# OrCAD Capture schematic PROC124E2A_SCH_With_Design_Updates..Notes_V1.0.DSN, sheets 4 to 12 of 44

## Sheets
4 12. SOC POWER SUPPLY PMIC: size C; title: SOC POWER SUPPLY PMIC
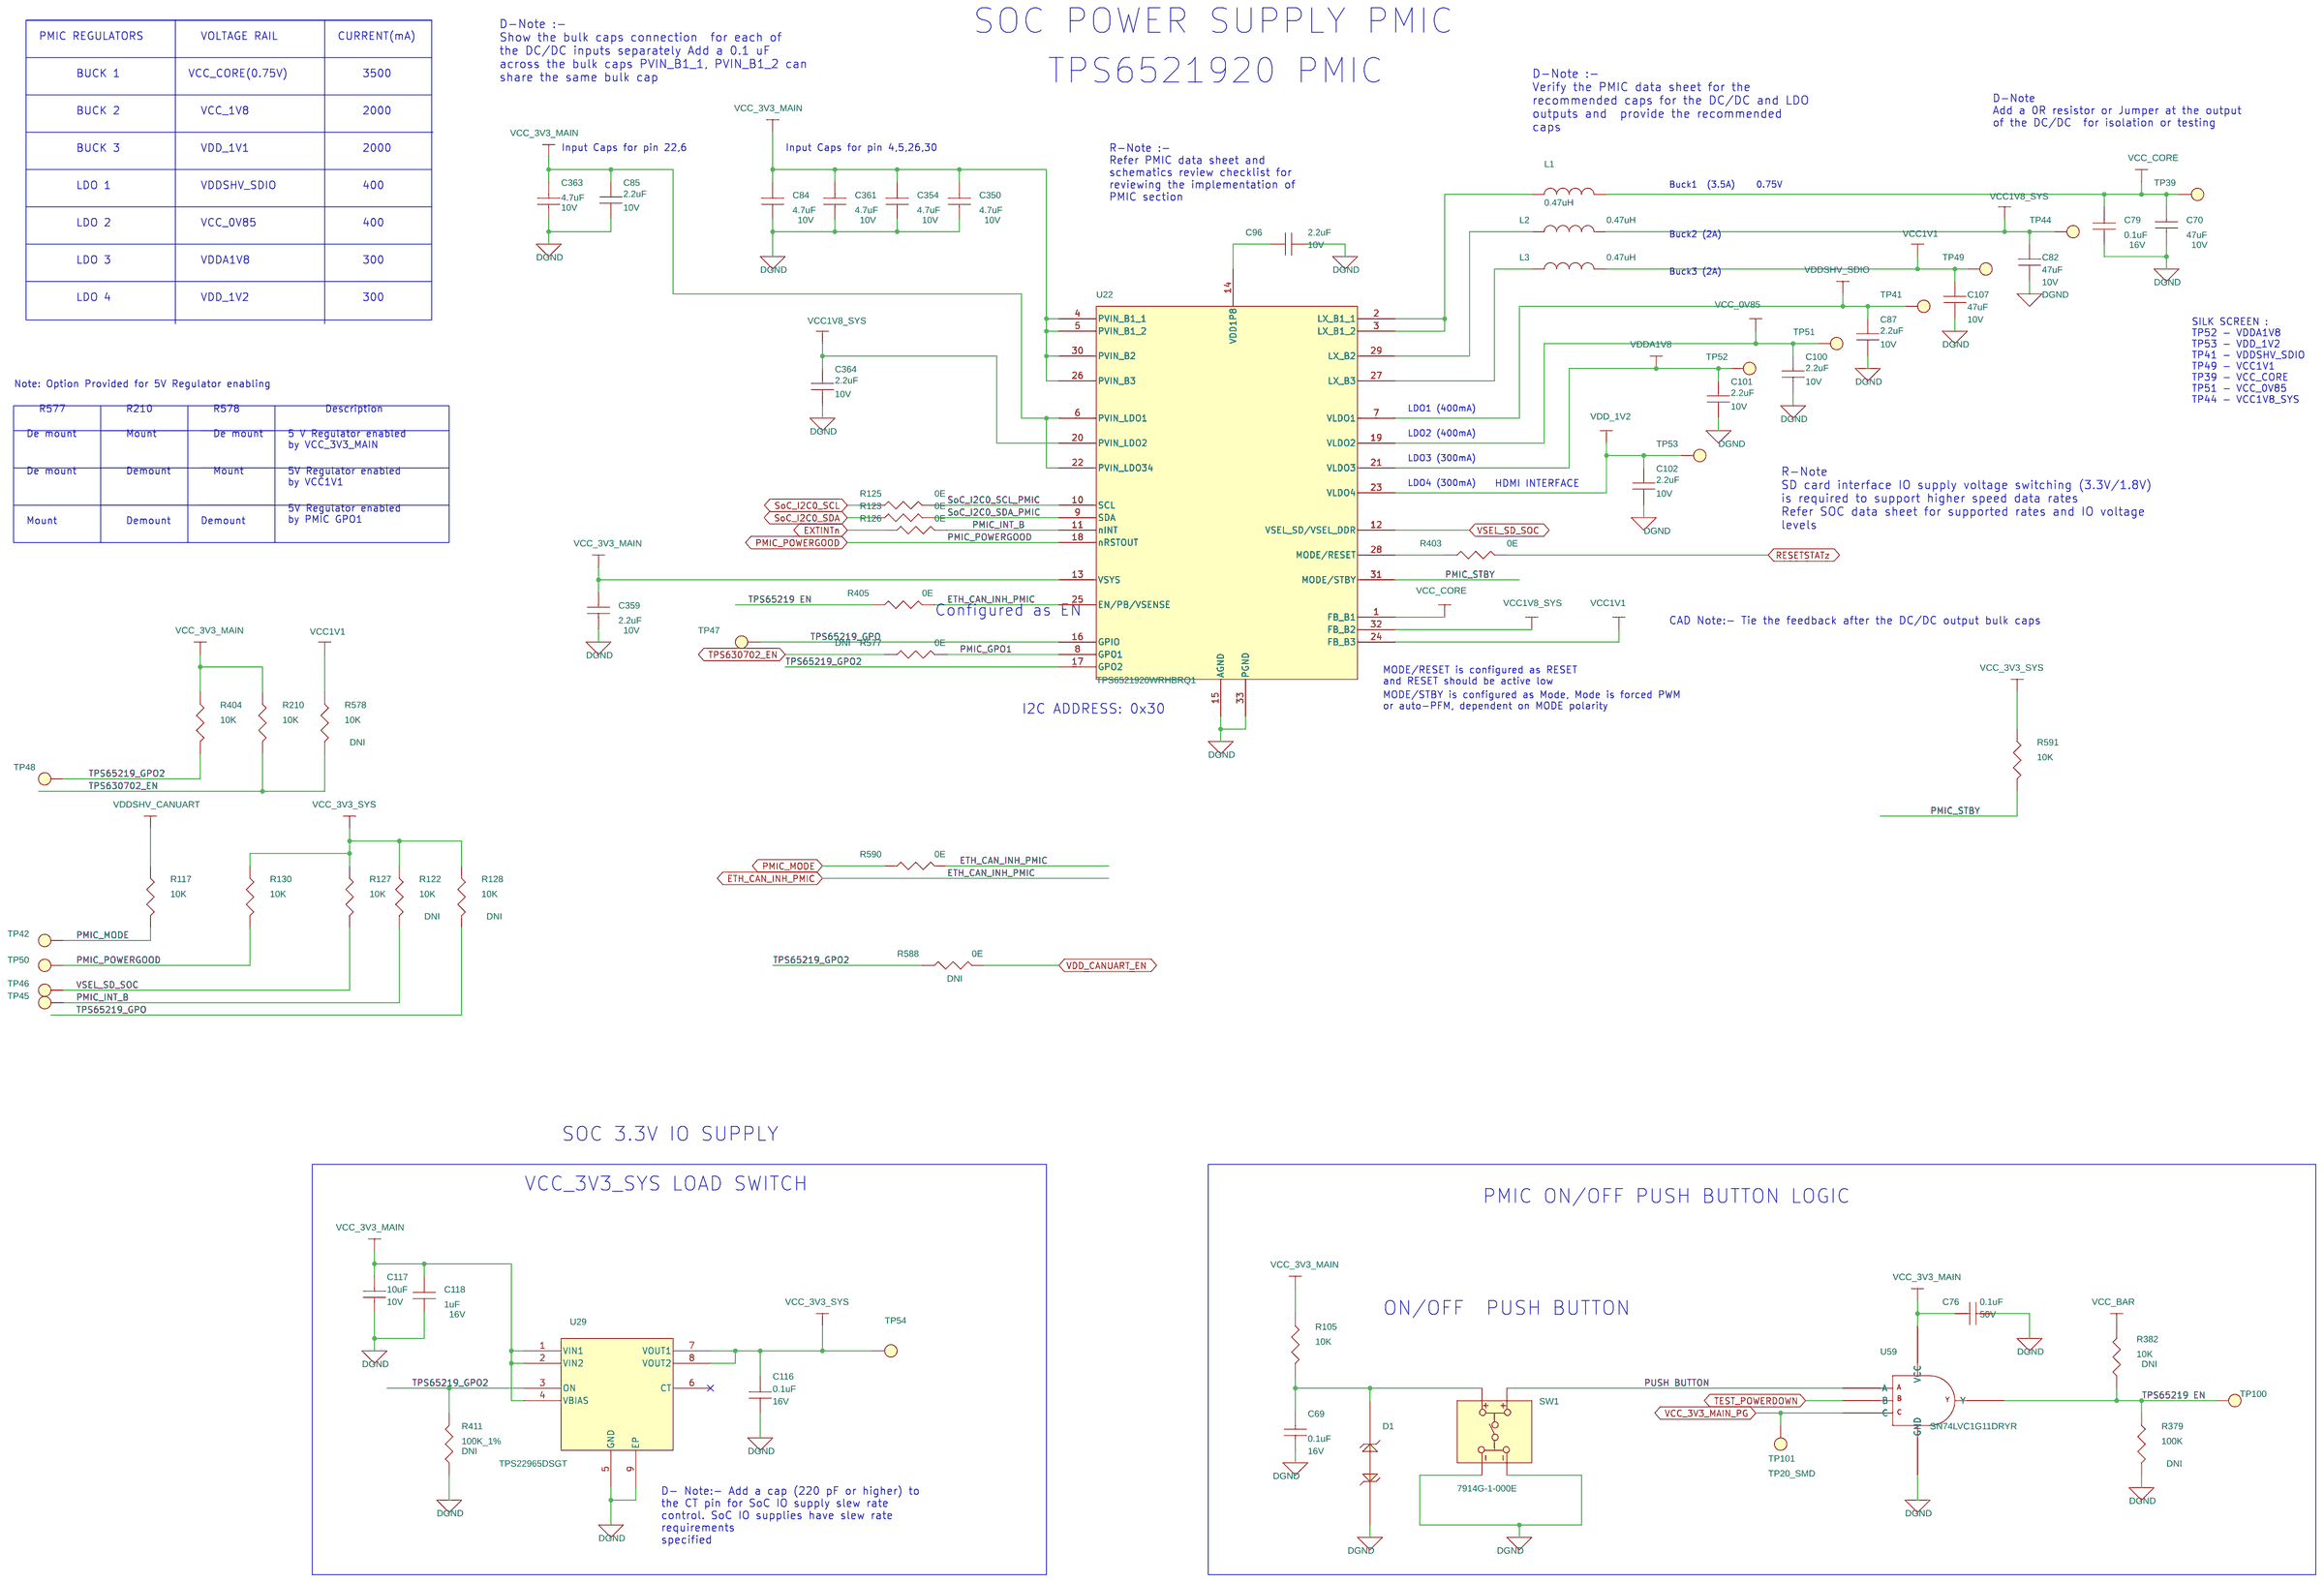
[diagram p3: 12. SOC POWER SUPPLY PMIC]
5 01. TABLE OF CONTENTS: title: TABLE OF CONTENTS
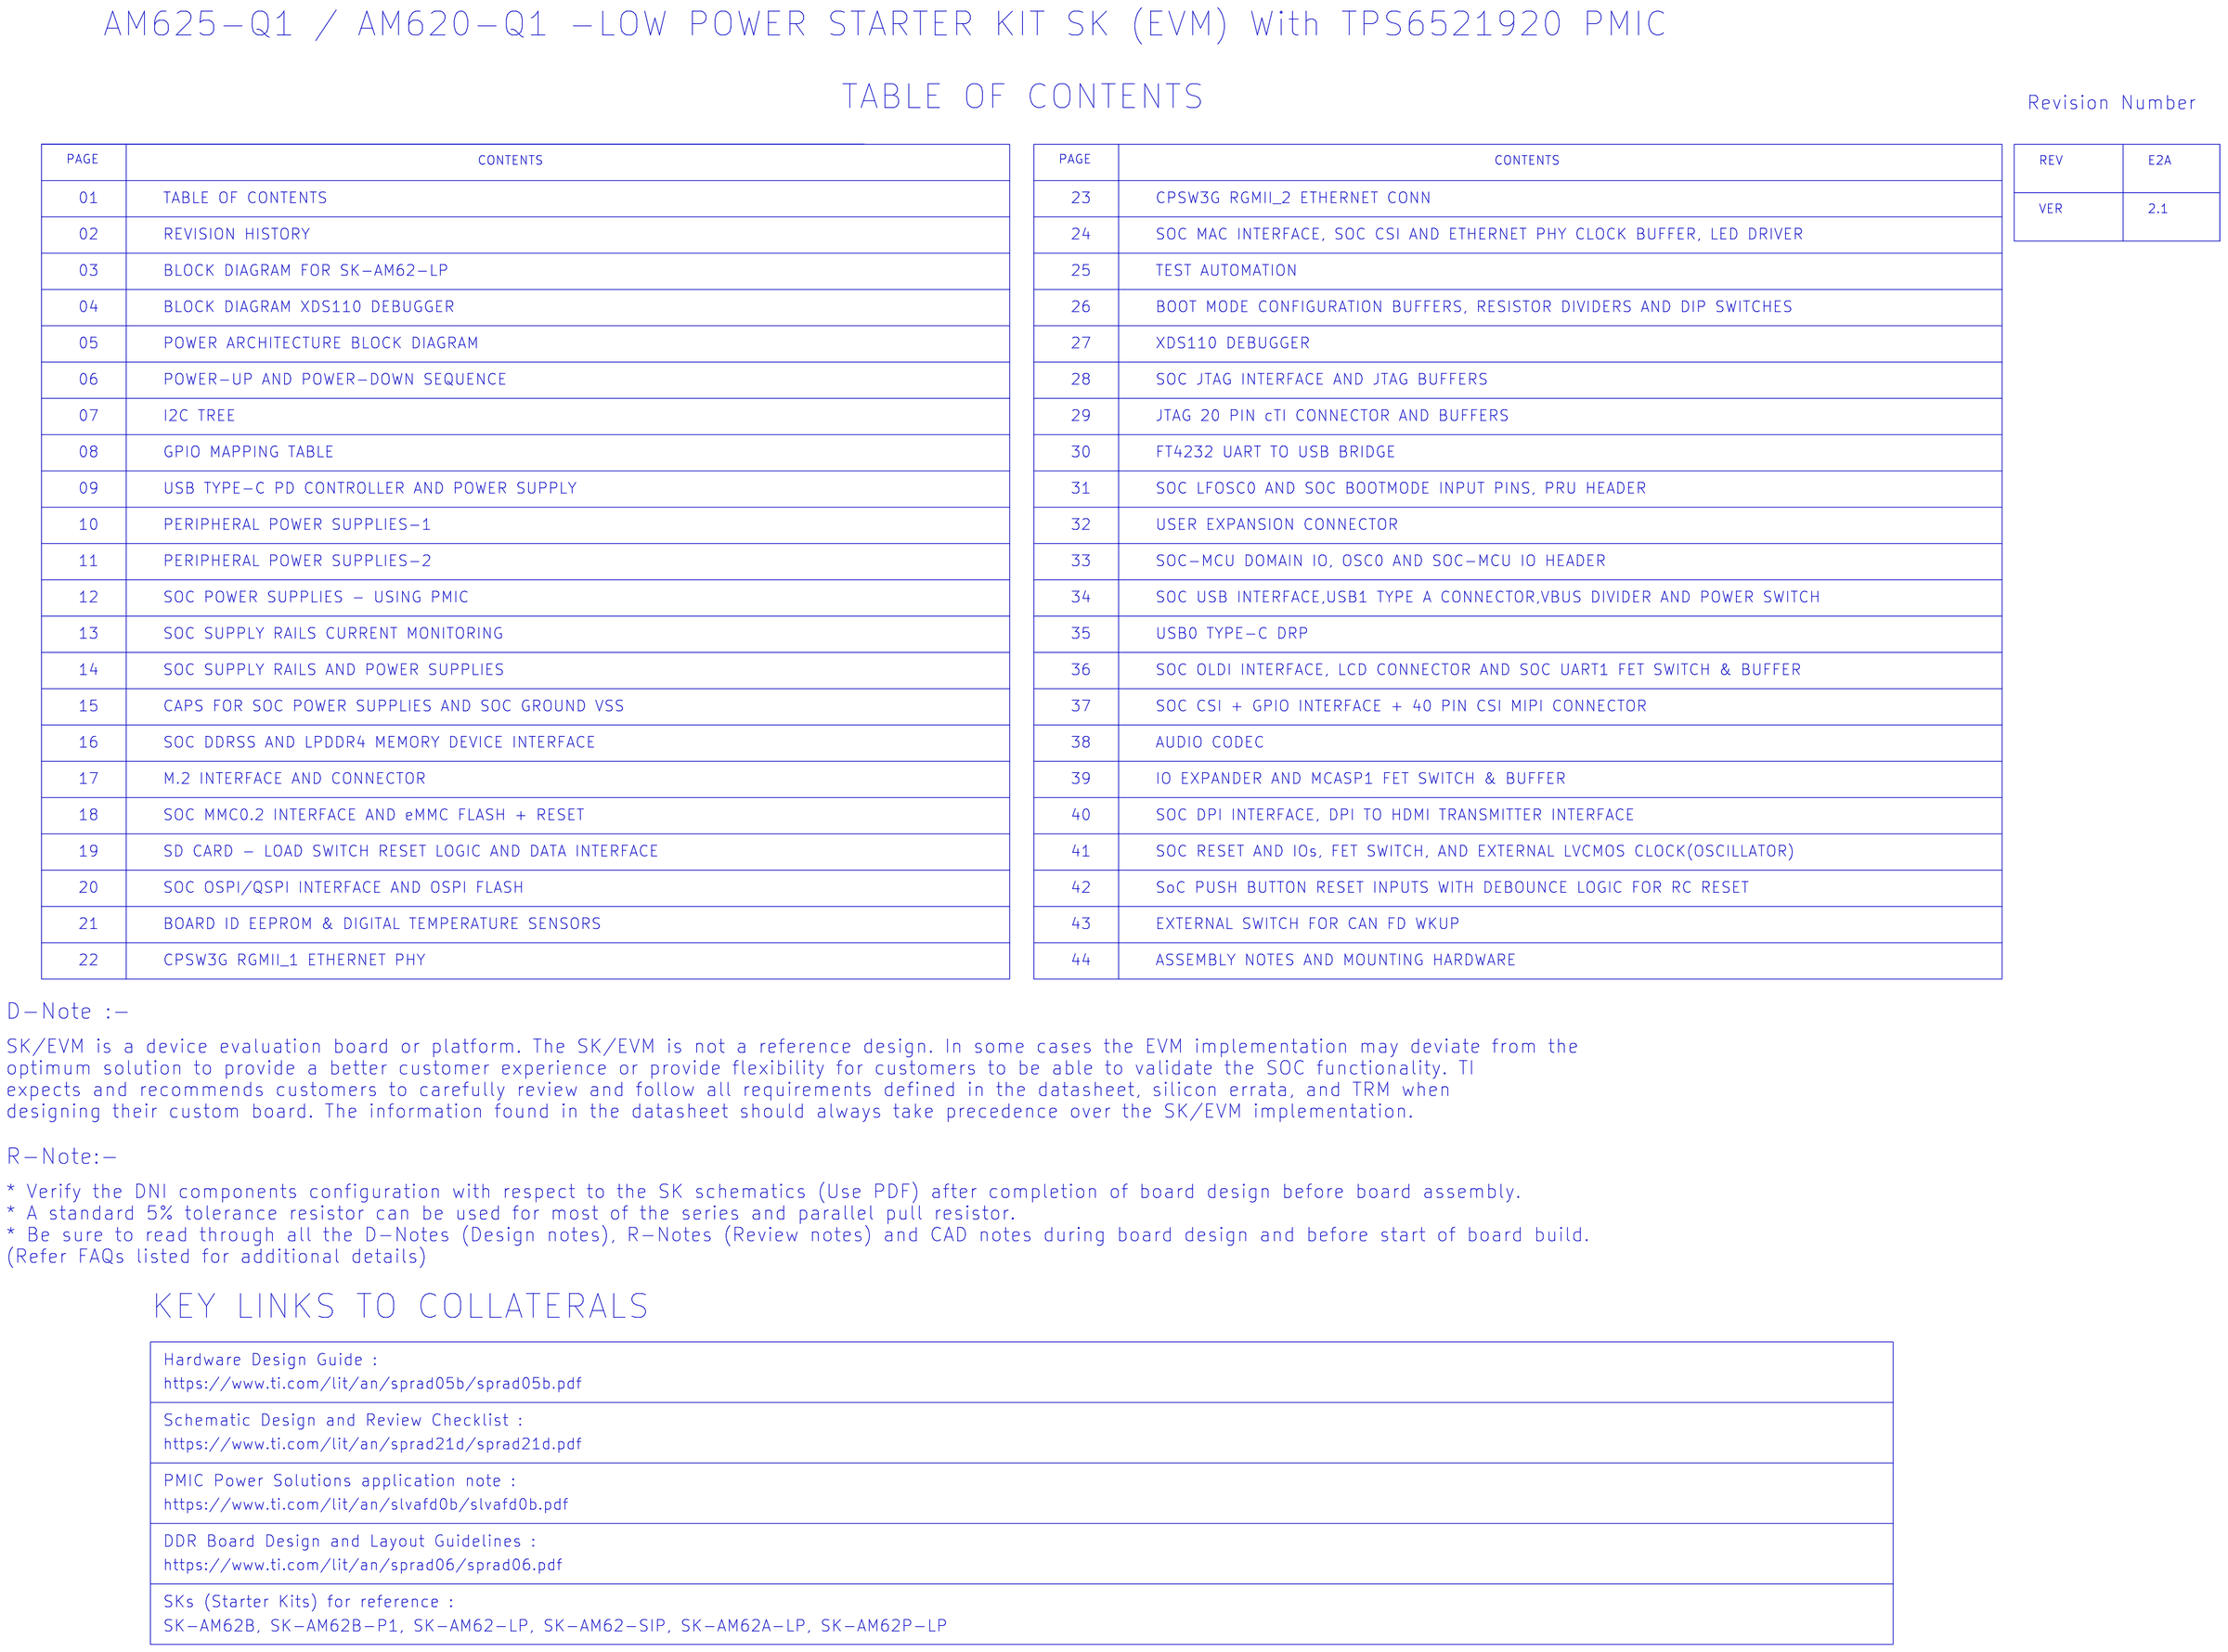
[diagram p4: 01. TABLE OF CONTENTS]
6 02. REVISION HISTORY: title: REVISION HISTORY
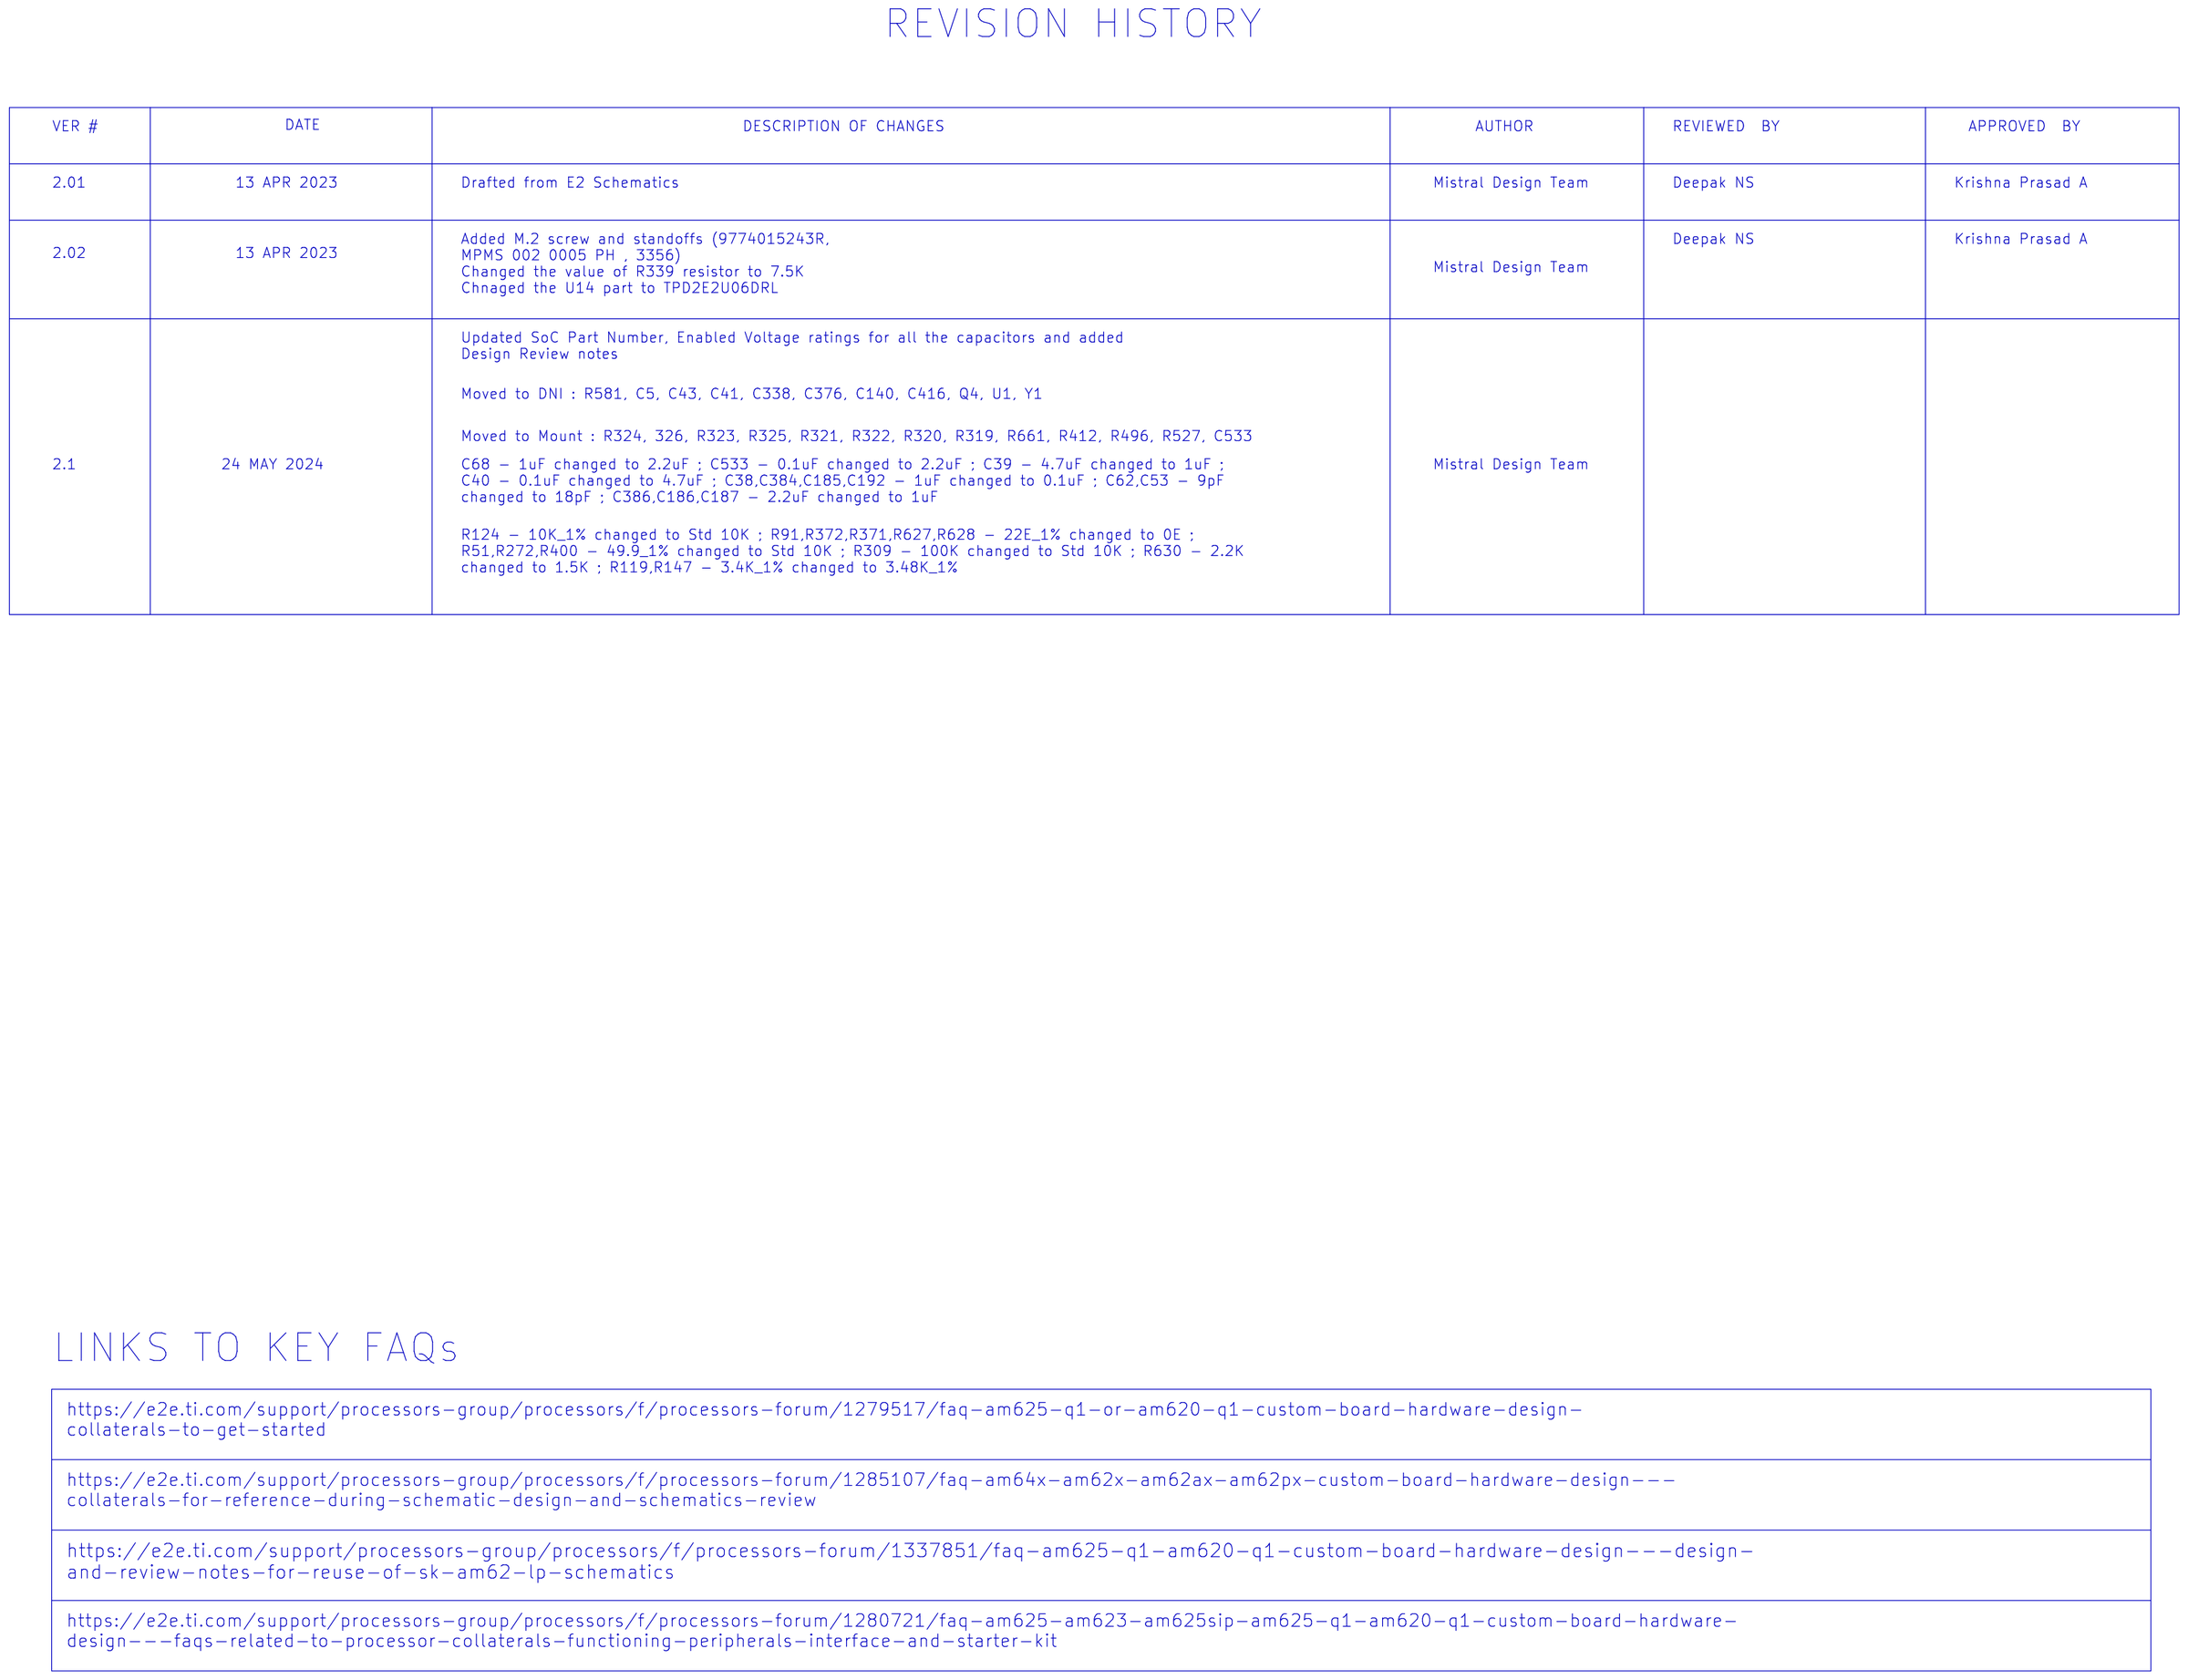
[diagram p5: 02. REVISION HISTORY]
7 03. BLOCK DGM AM62X-LP-SKEVM: title: BLOCK DIAGRAM AM62Q-LP_ SKEVM
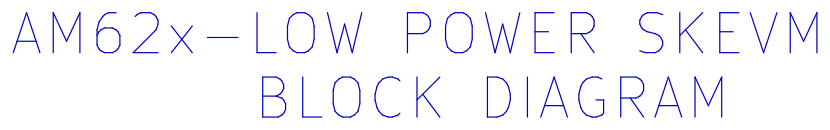
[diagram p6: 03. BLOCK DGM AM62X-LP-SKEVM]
8 04. BLOCK DIAGRAM_XDS110: title: BLOCK DIAGRAM_XDS110
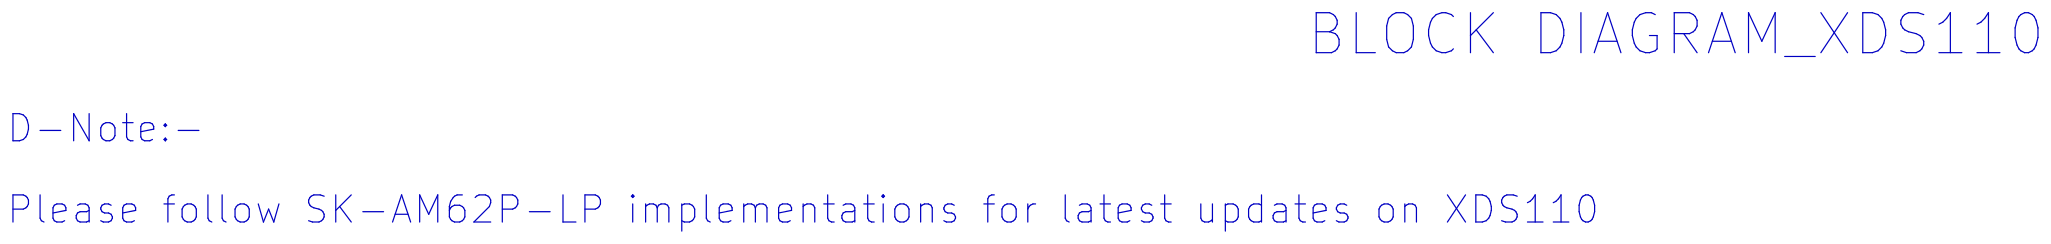
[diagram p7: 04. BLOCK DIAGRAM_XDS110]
9 05. POWER BLOCK DGM: title: POWER BLOCK DGM
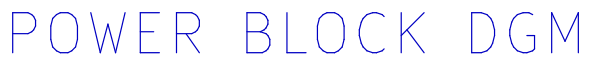
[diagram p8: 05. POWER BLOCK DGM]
10 06. POWER SEQUENCE: title: POWER SEQUENCE
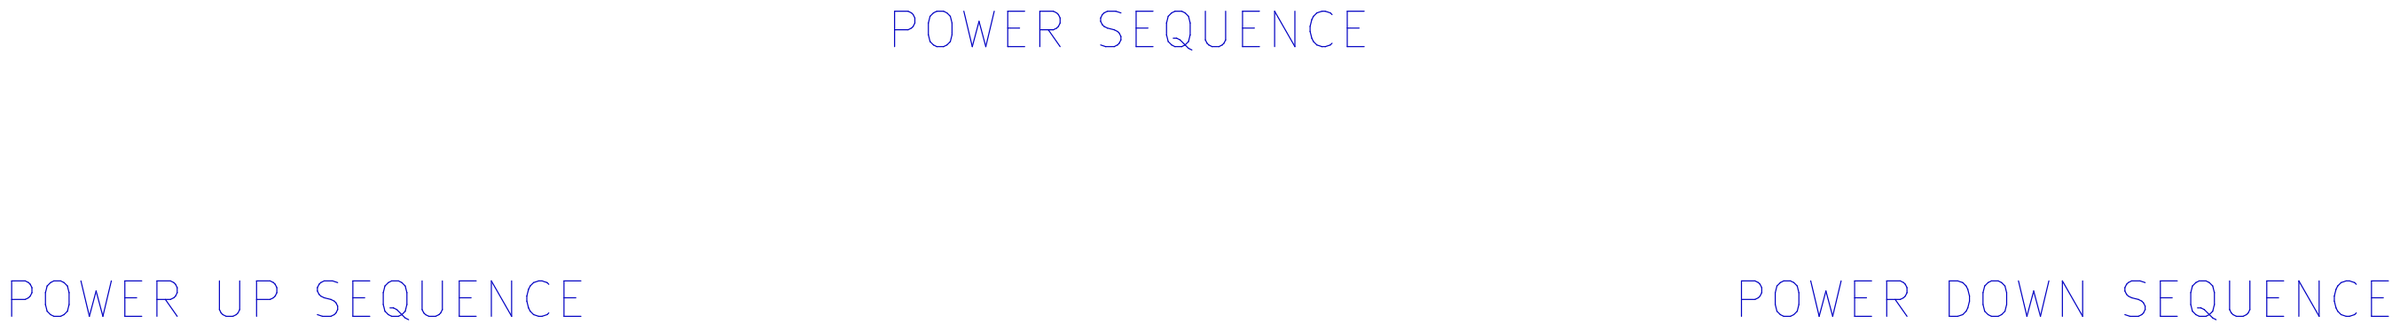
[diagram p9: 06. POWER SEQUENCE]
11 07. I2C TREE: title: I2C TREE
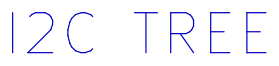
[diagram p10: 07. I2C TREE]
12 08. GPIO MAPPING TABLE: title: GPIO MAPPING TABLE
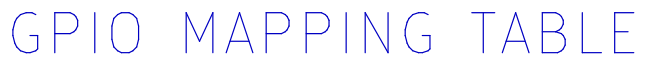
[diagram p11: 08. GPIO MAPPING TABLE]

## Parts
C69  0.1uF  [CAP0201_0-5]
C70  47uF  [CAP1206_2]
C76  0.1uF  [CAP0402_0-75]
C79  0.1uF  [CAP0201_0-5]
C82  47uF  [CAP1206_2]
C84  4.7uF  [CAP0402_0-75]
C85  2.2uF  [CAP0201_0-5]
C87  2.2uF  [CAP0201_0-5]
C96  2.2uF  [CAP0201_0-5]
C100  2.2uF  [CAP0201_0-5]
C101  2.2uF  [CAP0201_0-5]
C102  2.2uF  [CAP0201_0-5]
C107  47uF  [CAP1206_2]
C116  0.1uF  [CAP0201_0-5]
C117  10uF  [CAP0402_0-75]
C118  1uF  [CAP0201_0-5]
C350  4.7uF  [CAP0402_0-75]
C354  4.7uF  [CAP0402_0-75]
C359  2.2uF  [CAP0201_0-5]
C361  4.7uF  [CAP0402_0-75]
C363  4.7uF  [CAP0402_0-75]
C364  2.2uF  [CAP0201_0-5]
D1  TPD1E10B06DPYR  [DIO_DFN0402_0-5]
L1  0.47uH  [IND1008_1-2]
L2  0.47uH  [IND0806_1-2]
L3  0.47uH  [IND0806_1-2]
R105  10K  [RES0201_0-5]
R117  10K  [RES0201_0-5]
R122  10K  [RES0201_0-5]
R123  0E  [RES0201_0-5]
R125  0E  [RES0201_0-5]
R126  0E  [RES0201_0-5]
R127  10K  [RES0201_0-5]
R128  10K  [RES0201_0-5]
R130  10K  [RES0201_0-5]
R210  10K  [RES0201_0-5]
R379  100K  [RES0201_0-5]
R382  10K  [RES0201_0-5]
R403  0E  [RES0201_0-5]
R404  10K  [RES0201_0-5]
R405  0E  [RES0201_0-5]
R411  100K_1%  [RES0402_0-5]
R577  0E  [RES0201_0-5]
R578  10K  [RES0201_0-5]
R588  0E  [RES0201_0-5]
R590  0E  [RES0201_0-5]
R591  10K  [RES0201_0-5]
SW1  7914G-1-000E  [SW4_100X216_200X200_SMD_4-2]
TP39  TP20_SMD  [TP20_SMD]
TP41  TP20_SMD  [TP20_SMD]
TP42  TP20_SMD  [TP20_SMD]
TP44  TP20_SMD  [TP20_SMD]
TP45  TP20_SMD  [TP20_SMD]
TP46  TP20_SMD  [TP20_SMD]
TP47  TP20_SMD  [TP20_SMD]
TP48  TP20_SMD  [TP20_SMD]
TP49  TP20_SMD  [TP20_SMD]
TP50  TP20_SMD  [TP20_SMD]
TP51  TP20_SMD  [TP20_SMD]
TP52  TP20_SMD  [TP20_SMD]
TP53  TP20_SMD  [TP20_SMD]
TP54  TP20_SMD  [TP20_SMD]
TP100  TP20_SMD  [TP20_SMD]
TP101  TP20_SMD  [TP20_SMD]
U22  TPS6521920WRHBRQ1  [QFN32_19-68_200X200_1_EP3-8]
U29  TPS22965DSGT  [WSON8_19-68_80X80_0-8]
U59  SN74LVC1G11DRYR  [SON6_SN74LVC2G17_40X60_0-6]

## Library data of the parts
C69 C116 = CAP: CAP CERAMIC 0.1uF 16V 10% X5R 0201; Alt_Mfr_name: YAGEO AMERICA; Alt_Mfr_part_number: CC0402KRX5R8BB104; Chkd/date: MANIRAJA/230118; Crtd /date: MANIRAJA/230118; Custom_Duty: 15%; Customs_HS_Code: 85322990; Distributor_name: DIGIKEY; Distributor_part_number: 490-14305-1-ND; Footprint Path: Y:\MIS_DATABASE\Library\ALTIUM_TOOL\PCB_FOOTPRINTS\Altium_Footprint_Lib.PcbLib; Height: 0.33MM; Library Path: Y:\MIS_DATABASE\Library\ALTIUM_TOOL\SCHEMATICS_PARTS\MS_DISCRETE_Library.schlib; Mfr_name: MURATA; Mfr_part_number: GRM033R61C104KE14D; Mistral Part No: 120009030072-R; Package: 0201; Part_type: CAPACITORS\CERAMIC; Project: TI_MAXIE_CPB; RoHS: RoHS; Temperature: -55°C+85°C; Tolerance: 10%; Voltage: 16V; Wattage: NA; Weight: 0.33mg; Datasheet: Y:\MIS_DATABASE\DATASHEETS\CAPACITORS\GRM033R61C104KE14.PDF
C70 = CAP: CAP CERAMIC 47uF 10V 10% X5R 1206; Chkd/date: MANIRAJA/260219; Crtd /date: JEBRAN/090316; Custom_Duty: 15%; Customs_HS_Code: 85322990; Distributor_name: DIGIKEY; Distributor_part_number: 490-9673-1-ND; Footprint Path: Y:\MIS_DATABASE\Library\ALTIUM_TOOL\PCB_FOOTPRINTS\Altium_Footprint_Lib.PcbLib; Height: 1.80MM; Library Path: Y:\MIS_DATABASE\Library\ALTIUM_TOOL\SCHEMATICS_PARTS\MS_DISCRETE_Library.schlib; Manufacturer: MURATA; Mfr_name: MURATA; Mfr_part_number: GRM31CR61A476KE15L; Mistral Part No: 120019020018-R; Package: 1206; Part_type: CAPACITORS\CERAMIC; Project: RCI_DLS_CARD; RoHS: RoHS; Temperature: -55°C+85°C; Tolerance: 10%; Voltage: 10V; Wattage: NA; Weight: 40mg; Datasheet: Y:\MIS_DATABASE\DATASHEETS\CAPACITORS\MURATA-GXX-SER_NOV17.PDF
C76 = CAP: CAP CERAMIC 0.1uF 50V 10% X7R 0402; Alt_Mfr_name: YAGEO AMERICA; Alt_Mfr_part_number: CC0402KRX5R8BB104; Chkd/date: MANIRAJA/261020; Crtd /date: ALVY/211020; Custom_Duty: 15%; Customs_HS_Code: 85322990; Distributor_name: DIGIKEY; Distributor_part_number: 490-10700-1-ND; Footprint Path: Y:\MIS_DATABASE\Library\ALTIUM_TOOL\PCB_FOOTPRINTS\Altium_Footprint_Lib.PcbLib; Height: 0.55MM; Library Path: Y:\MIS_DATABASE\Library\ALTIUM_TOOL\SCHEMATICS_PARTS\MS_DISCRETE_Library.schlib; Mfr_name: MURATA; Mfr_part_number: GRM155R71H104KE14D; Mistral Part No: 120011100014-R; Package: 0402; Part_type: CAPACITORS\CERAMIC; Project: J7_CP; RoHS: RoHS; Temperature: -55°C+125°C; Tolerance: 10%; Voltage: 50V; Wattage: NA; Weight: 3.1mg; Datasheet: Y:\MIS_DATABASE\DATASHEETS\CAPACITORS\GRM155R71H104KE14.PDF
C79 = CAP: CAP CERAMIC 0.1uF 16V 10% X5R 0201; Chkd/date: MANIRAJA/230118; Crtd /date: MANIRAJA/230118; Custom_Duty: 15%; Customs_HS_Code: 85322990; Distributor_name: DIGIKEY; Distributor_part_number: 490-14305-1-ND; Footprint Path: Y:\MIS_DATABASE\Library\ALTIUM_TOOL\PCB_FOOTPRINTS\Altium_Footprint_Lib.PcbLib; Height: 0.33MM; Library Path: Y:\MIS_DATABASE\Library\ALTIUM_TOOL\SCHEMATICS_PARTS\MS_DISCRETE_Library.schlib; Mfr_name: MURATA; Mfr_part_number: GRM033R61C104KE14D; Mistral Part No: 120009030072-R; Package: 0201; Part_type: CAPACITORS\CERAMIC; Project: TI_MAXIE_CPB; RoHS: RoHS; Temperature: -55°C+85°C; Tolerance: 10%; Voltage: 16V; Wattage: NA; Weight: 0.33mg; Datasheet: Y:\MIS_DATABASE\DATASHEETS\CAPACITORS\GRM033R61C104KE14.PDF
C82 C107 = CAP: CAP CERAMIC 47uF 10V 10% X5R 1206; Chkd/date: MANIRAJA/260219; Crtd /date: JEBRAN/090316; Custom_Duty: 15%; Customs_HS_Code: 85322990; Distributor_name: DIGIKEY; Distributor_part_number: 490-9673-1-ND; Footprint Path: Y:\MIS_DATABASE\Library\ALTIUM_TOOL\PCB_FOOTPRINTS\Altium_Footprint_Lib.PcbLib; Height: 1.80MM; Library Path: Y:\MIS_DATABASE\Library\ALTIUM_TOOL\SCHEMATICS_PARTS\MS_DISCRETE_Library.schlib; Mfr_name: MURATA; Mfr_part_number: GRM31CR61A476KE15L; Mistral Part No: 120019020018-R; Package: 1206; Part_type: CAPACITORS\CERAMIC; Project: RCI_DLS_CARD; RoHS: RoHS; Temperature: -55°C+85°C; Tolerance: 10%; Voltage: 10V; Wattage: NA; Weight: 40mg; Datasheet: Y:\MIS_DATABASE\DATASHEETS\CAPACITORS\MURATA-GXX-SER_NOV17.PDF
C84 C350 C354 C361 C363 = CAP: CAP CERAMIC 4.7uF 10V 20% X5R 0402; Chkd/date: MANIRAJA/110718; Crtd /date: ALVY/110718; Custom_Duty: 15%; Customs_HS_Code: 85322990; Distributor_name: DIGIKEY; Distributor_part_number: 490-14306-1-ND; Footprint Path: Y:\MIS_DATABASE\Library\ALTIUM_TOOL\PCB_FOOTPRINTS\Altium_Footprint_Lib.PcbLib; Height: 0.65MM; Library Path: Y:\MIS_DATABASE\Library\ALTIUM_TOOL\SCHEMATICS_PARTS\MS_DISCRETE_Library.schlib; Mfr_name: MURATA; Mfr_part_number: GRM155R61A475MEAAD; Mistral Part No: 120012060002-R; Package: 0402; Part_type: CAPACITORS\CERAMIC; Project: TI_J7SVB_PCIE_ADD-ON-CARD; RoHS: RoHS; Temperature: -55°C+85°C; Tolerance: 20%; Voltage: 10V; Wattage: NA; Weight: 14mg; Datasheet: Y:\MIS_DATABASE\DATASHEETS\CAPACITORS\GRM155R61A475MEAAD.PDF
C85 C87 C96 C100-C102 C364 = CAP: CAP CERAMIC 2.2uF 10V 10% X5R 0201; Chkd/date: MANIRAJA/220918; Crtd /date: MANIRAJA/220918; Custom_Duty: 15%; Customs_HS_Code: 85322990; Distributor_name: DIGIKEY; Distributor_part_number: 490-13227-1-ND; Footprint Path: Y:\MIS_DATABASE\Library\ALTIUM_TOOL\PCB_FOOTPRINTS\Altium_Footprint_Lib.PcbLib; Height: 0.39MM; Library Path: Y:\MIS_DATABASE\Library\ALTIUM_TOOL\SCHEMATICS_PARTS\MS_DISCRETE_Library.schlib; Mfr_name: MURATA; Mfr_part_number: GRM033R61A225KE47D; Mistral Part No: 120018090044-R; Package: 0201; Part_type: CAPACITORS\CERAMIC; Project: TI_60GHz-AOP; RoHS: RoHS; Temperature: -55°C+85°C; Tolerance: 10%; Voltage: 10V; Wattage: NA; Weight: 0.33mg; Datasheet: Y:\MIS_DATABASE\DATASHEETS\CAPACITORS\GRM033R61A225KE47D.PDF
C117 = CAP: CAP CERAMIC 10uF 10V 20% X5R 0402; Chkd/date: MANIRAJA/300520; Crtd /date: ALVY/260520; Custom_Duty: 15%; Customs_HS_Code: 85322990; Distributor_name: DIGIKEY; Distributor_part_number: 490-GRM155R61A106ME11DTR-ND; Footprint Path: Y:\MIS_DATABASE\Library\ALTIUM_TOOL\PCB_FOOTPRINTS\Altium_Footprint_Lib.PcbLib; Height: 0.55MM; Library Path: Y:\MIS_DATABASE\Library\ALTIUM_TOOL\SCHEMATICS_PARTS\MS_DISCRETE_Library.schlib; Mfr_name: MURATA; Mfr_part_number: GRM155R61A106ME11D; Mistral Part No: 120013110019-R; Package: 0402; Part_type: CAPACITORS\CERAMIC; Project: QCS610_NANOSOM; RoHS: RoHS; Temperature: -55°C+85°C; Tolerance: 20%; Voltage: 10V; Wattage: NA; Weight: 3.1mg; Datasheet: Y:\MIS_DATABASE\DATASHEETS\CAPACITORS\MURATA-GXX-SER_NOV17.PDF
C118 = CAP: CAP CERAMIC 1uF 16V 20% X5R 0201; Chkd/date: MANIRAJA/300520; Crtd /date: ALVY/260520; Custom_Duty: 15%; Customs_HS_Code: 85322990; Distributor_name: DIGIKEY; Distributor_part_number: 490-18654-1-ND; Footprint Path: Y:\MIS_DATABASE\Library\ALTIUM_TOOL\PCB_FOOTPRINTS\Altium_Footprint_Lib.PcbLib; Height: 0.39MM; Library Path: Y:\MIS_DATABASE\Library\ALTIUM_TOOL\SCHEMATICS_PARTS\MS_DISCRETE_Library.schlib; Mfr_name: MURATA; Mfr_part_number: GRM033R61C105ME15D; Mistral Part No: 120018090038-R; Package: 0201; Part_type: CAPACITORS\CERAMIC; Project: QCS610_NANOSOM; RoHS: RoHS; Temperature: -55°C+85°C; Tolerance: 20%; Voltage: 16V; Wattage: NA; Weight: 0.33mg; Datasheet: Y:\MIS_DATABASE\DATASHEETS\CAPACITORS\GRM033R61C105ME15.PDF
C359 = CAP: CAP CERAMIC 2.2uF 10V 10% X5R 0201; Alt_Mfr_name: YAGEO AMERICA; Alt_Mfr_part_number: CC0402KRX5R8BB104; Chkd/date: MANIRAJA/220918; Crtd /date: MANIRAJA/220918; Custom_Duty: 15%; Customs_HS_Code: 85322990; Distributor_name: DIGIKEY; Distributor_part_number: 490-13227-1-ND; Footprint Path: Y:\MIS_DATABASE\Library\ALTIUM_TOOL\PCB_FOOTPRINTS\Altium_Footprint_Lib.PcbLib; Height: 0.39MM; Library Path: Y:\MIS_DATABASE\Library\ALTIUM_TOOL\SCHEMATICS_PARTS\MS_DISCRETE_Library.schlib; Mfr_name: MURATA; Mfr_part_number: GRM033R61A225KE47D; Mistral Part No: 120018090044-R; Package: 0201; Part_type: CAPACITORS\CERAMIC; Project: TI_60GHz-AOP; RoHS: RoHS; Temperature: -55°C+85°C; Tolerance: 10%; Voltage: 10V; Wattage: NA; Weight: 0.33mg; Datasheet: Y:\MIS_DATABASE\DATASHEETS\CAPACITORS\GRM033R61A225KE47D.PDF
D1 = DIODE_SOD323: DIODE 1CH ESD PROTECTION X1SON2; Chkd/date: MANIRAJA/040420; Crtd /date: VASANTHA/181114; Custom_Duty: 15%; Customs_HS_Code: 85423100; Distributor_name: DIGIKEY; Distributor_part_number: 296-30406-1-ND; Footprint Path: Y:\MIS_DATABASE\Library\ALTIUM_TOOL\PCB_FOOTPRINTS\Altium_Footprint_Lib.PcbLib; Height: 0.45MM; Library Path: Y:\MIS_DATABASE\Library\ALTIUM_TOOL\SCHEMATICS_PARTS\MS_DISCRETE_Library.schlib; Mfr_name: TEXAS INSTRUMENTS; Mistral Part No: 130014110022-R; Package: X1SON2; Part_type: DIODE; Project: GALILEO_EVM; RoHS: RoHS; Temperature: -40°C+125°C; Tolerance: NA; Voltage: NA; Wattage: NA; Weight: 1mg; Datasheet: Y:\MIS_DATABASE\DATASHEETS\ICS\INTERFACE\TPD1E10B06-SER.PDF
L1 = INDUCTOR: IND CHIP 0.47uH 4.9A 20% 1008; Chkd/date: ALVY/110322; Crtd /date: TAMILARASU/100322; Custom_Duty: 24%; Customs_HS_Code: 85437099; Distributor_name: DIGIKEY; Distributor_part_number: 490-13049-1-ND; Footprint Path: Y:\MIS_DATABASE\Library\ALTIUM_TOOL\PCB_FOOTPRINTS\Altium_Footprint_Lib.PcbLib; Height: 1.20MM; Library Path: Y:\MIS_DATABASE\Library\ALTIUM_TOOL\SCHEMATICS_PARTS\MS_DISCRETE_Library.schlib; Mfr_name: MURATA; Mfr_part_number: DFE252012F-R47M=P2; Mistral Part No: 130022030019-R; Package: 1008; Project: TI_AM62Q_SKEVM_xNAND_BRD; RoHS: RoHS; Temperature: -40°C+125°C; Tolerance: 20%; Voltage: NA; Wattage: NA; Weight: NA; Datasheet: Y:\MIS_DATABASE\DATASHEETS\DISCRETES\INDUCTORS\DFE252012F.PDF
L2 L3 = INDUCTOR: IND CHIP 0.47uH 4.5A 20% 0806; Chkd/date: MANIRAJA/121020; Crtd /date: ALVY/121020; Custom_Duty: 24%; Customs_HS_Code: 85437099; Distributor_name: DIGIKEY; Distributor_part_number: DFE201612E-R47M=P2-ND; Footprint Path: Y:\MIS_DATABASE\Library\ALTIUM_TOOL\PCB_FOOTPRINTS\Altium_Footprint_Lib.PcbLib; Height: 1.20MM; Library Path: Y:\MIS_DATABASE\Library\ALTIUM_TOOL\SCHEMATICS_PARTS\MS_DISCRETE_Library.schlib; Mfr_name: MURATA; Mfr_part_number: DFE201612E-R47M=P2; Mistral Part No: 130020100030-R; Package: 0806; Project: AM64X_SKEVM; RoHS: RoHS; Temperature: -40°C+125°C; Tolerance: 20%; Voltage: NA; Wattage: NA; Weight: 18.8mg; Datasheet: Y:\MIS_DATABASE\DATASHEETS\DISCRETES\INDUCTORS\DFE201612E.PDF
R105 R117 R127 R130 R210 R404 R591 = RESISTOR: RES 10K 1/20W 5% 0201; Chkd/date: MANIRAJA/050517; Crtd /date: MANIRAJA/050517; Custom_Duty: 15%; Customs_HS_Code: 85332119; Distributor_name: DIGIKEY; Distributor_part_number: 311-10KNCT-ND; Footprint Path: Y:\MIS_DATABASE\Library\ALTIUM_TOOL\PCB_FOOTPRINTS\Altium_Footprint_Lib.PcbLib; Height: 0.26MM; Library Path: Y:\MIS_DATABASE\Library\ALTIUM_TOOL\SCHEMATICS_PARTS\MS_DISCRETE_Library.schlib; Mfr_name: YAGEO AMERICA; Mfr_part_number: RC0201JR-0710KL; Mistral Part No: 110010070051-R; Package: 0201; Part_type: RESISTORS\FIXED; Project: GOLDEN-I LITE; RoHS: RoHS; Temperature: -55°C+125°C; Tolerance: 5%; Voltage: NA; Wattage: 1/20W; Weight: 0.17mg; Datasheet: Y:\MIS_DATABASE\DATASHEETS\RESISTORS\RCXXXXL-SER_MAR18.PDF
R122 R128 R382 R578 = RESISTOR: RES 10K 1/20W 5% 0201; Assembly_Instruction: DNI; Chkd/date: MANIRAJA/050517; Crtd /date: MANIRAJA/050517; Custom_Duty: 15%; Customs_HS_Code: 85332119; Distributor_name: DIGIKEY; Distributor_part_number: 311-10KNCT-ND; Footprint Path: Y:\MIS_DATABASE\Library\ALTIUM_TOOL\PCB_FOOTPRINTS\Altium_Footprint_Lib.PcbLib; Height: 0.26MM; Library Path: Y:\MIS_DATABASE\Library\ALTIUM_TOOL\SCHEMATICS_PARTS\MS_DISCRETE_Library.schlib; Mfr_name: YAGEO AMERICA; Mfr_part_number: RC0201JR-0710KL; Mistral Part No: 110010070051-R; Package: 0201; Part_type: RESISTORS\FIXED; Project: GOLDEN-I LITE; RoHS: RoHS; Temperature: -55°C+125°C; Tolerance: 5%; Voltage: NA; Wattage: 1/20W; Weight: 0.17mg; Datasheet: Y:\MIS_DATABASE\DATASHEETS\RESISTORS\RCXXXXL-SER_MAR18.PDF
R123 R125 R403 = RESISTOR: RES 0E 1/20W JUMPER 0201; Chkd/date: MANIRAJA/290421; Crtd /date: ALVY/290421; Custom_Duty: 15%; Customs_HS_Code: 85332119; Distributor_name: DIGIKEY; Distributor_part_number: P15979CT-ND; Footprint Path: Y:\MIS_DATABASE\Library\ALTIUM_TOOL\PCB_FOOTPRINTS\Altium_Footprint_Lib.PcbLib; Height: 0.26MM; Library Path: Y:\MIS_DATABASE\Library\ALTIUM_TOOL\SCHEMATICS_PARTS\MS_DISCRETE_Library.schlib; Mfr_name: PANASONIC-ECG; Mfr_part_number: ERJ-1GN0R00C; Mistral Part No: 110009030078-R; Package: 0201; Part_type: RESISTORS\FIXED; Project: SRMS-SAR_BRD; RoHS: RoHS; Temperature: -55°C+125°C; Tolerance: NA; Voltage: NA; Wattage: 1/20W; Weight: 0.15mg; Datasheet: Y:\MIS_DATABASE\DATASHEETS\RESISTORS\PAN-ERJSER_NOV17.PDF
R126 R405 R590 = RESISTOR: RES 0E 1/20W 5% 0201; Chkd/date: NAVEED/301214; Crtd /date: MUDDU/120710; Custom_Duty: 15%; Customs_HS_Code: 85332119; Distributor_name: DIGIKEY; Distributor_part_number: 311-0.0NCT-ND; Footprint Path: Y:\MIS_DATABASE\Library\ALTIUM_TOOL\PCB_FOOTPRINTS\Altium_Footprint_Lib.PcbLib; Height: 0.26MM; Library Path: Y:\MIS_DATABASE\Library\ALTIUM_TOOL\SCHEMATICS_PARTS\MS_DISCRETE_Library.schlib; Mfr_name: YAGEO AMERICA; Mfr_part_number: RC0201JR-070RL; Mistral Part No: 110010070067-R; Package: 0201; Part_type: RESISTORS\FIXED; Project: PB_BUGBASE; RoHS: RoHS; Temperature: -55°C+125°C; Tolerance: 5%; Voltage: NA; Wattage: 1/20W; Weight: 0.17mg; Datasheet: Y:\MIS_DATABASE\DATASHEETS\RESISTORS\RCXXXXL-SER_MAR18.PDF
R379 = RESISTOR: RES 100K 1/20W 5% 0201; Assembly_Instruction: DNI; Chkd/date: PRAVEEN/080922; Crtd /date: TAMILARASU/080922; Custom_Duty: 15%; Customs_HS_Code: 85332119; Distributor_name: DIGIKEY; Distributor_part_number: P123223CT-ND; Footprint Path: Y:\MIS_DATABASE\Library\ALTIUM_TOOL\PCB_FOOTPRINTS\Altium_Footprint_Lib.PcbLib; Height: 0.26MM; Library Path: Y:\MIS_DATABASE\Library\ALTIUM_TOOL\SCHEMATICS_PARTS\MS_DISCRETE_Library.schlib; Mfr_name: PANASONIC-ECG; Mfr_part_number: ERJ-1GNJ104C; Mistral Part No: 110022090005-R; Package: 0201; Part_type: RESISTORS\FIXED; Project: SK AM62Q LP EVM BRD; RoHS: RoHS; Temperature: -55°C+125°C; Tolerance: 5%; Voltage: NA; Wattage: 1/20W; Weight: 0.15mg; Datasheet: Y:\MIS_DATABASE\DATASHEETS\RESISTORS\PAN-ERJSER_NOV17.PDF
R411 = RESISTOR: RES 100K 1/10W 1% 0402; Assembly_Instruction: DNI; Chkd/date: VASANTHA/201216; Crtd /date: MAZHAR/130306; Custom_Duty: 15%; Customs_HS_Code: 85332119; Distributor_name: DIGIKEY; Distributor_part_number: P100KLCT-ND; Footprint Path: Y:\MIS_DATABASE\Library\ALTIUM_TOOL\PCB_FOOTPRINTS\Altium_Footprint_Lib.PcbLib; Height: 0.40MM; Library Path: Y:\MIS_DATABASE\Library\ALTIUM_TOOL\SCHEMATICS_PARTS\MS_DISCRETE_Library.schlib; Mfr_name: PANASONIC-ECG; Mfr_part_number: ERJ-2RKF1003X; Mistral Part No: 110009030187-R; Package: 0402; Part_type: RESISTORS\FIXED; Project: J32; RoHS: RoHS; Temperature: -55°C+155°C; Tolerance: 1%; Voltage: NA; Wattage: 1/10W; Weight: 0.8mg; Datasheet: Y:\MIS_DATABASE\DATASHEETS\RESISTORS\PAN-ERJSER_NOV17.PDF
R577 R588 = RESISTOR: RES 0E 1/20W 5% 0201; Assembly_Instruction: DNI; Chkd/date: NAVEED/301214; Crtd /date: MUDDU/120710; Custom_Duty: 15%; Customs_HS_Code: 85332119; Distributor_name: DIGIKEY; Distributor_part_number: 311-0.0NCT-ND; Footprint Path: Y:\MIS_DATABASE\Library\ALTIUM_TOOL\PCB_FOOTPRINTS\Altium_Footprint_Lib.PcbLib; Height: 0.26MM; Library Path: Y:\MIS_DATABASE\Library\ALTIUM_TOOL\SCHEMATICS_PARTS\MS_DISCRETE_Library.schlib; Mfr_name: YAGEO AMERICA; Mfr_part_number: RC0201JR-070RL; Mistral Part No: 110010070067-R; Package: 0201; Part_type: RESISTORS\FIXED; Project: PB_BUGBASE; RoHS: RoHS; Temperature: -55°C+125°C; Tolerance: 5%; Voltage: NA; Wattage: 1/20W; Weight: 0.17mg; Datasheet: Y:\MIS_DATABASE\DATASHEETS\RESISTORS\RCXXXXL-SER_MAR18.PDF
SW1 = 7914G-1-000E__7914G: SWITCH SPST-NO 4MM SQ SMD 7914G; Chkd/date: VASANTHA/271216; Crtd /date: BAVISH/051010; Custom_Duty: 24%; Customs_HS_Code: 85369090; Distributor_name: DIGIKEY; Distributor_part_number: 7914G-000ECT-ND; Height: 4.19MM; Library Ref: 7914G-1-000E _7914G; Mfr_name: BOURNS; Mistral Part No: 130015110004-R; Package: 7914G; Part_type: ELECTRO-MECHANICAL\SWITCH; Project: AAAUC; RoHS: RoHS; Temperature: -55°C+125°C; Tolerance: NA; Voltage: NA; Wattage: NA; Weight: NA; Datasheet: Y:\MIS_DATABASE\DATASHEETS\ICS\DIGITAL\COMBINATIONAL\7914G-1-000E.PDF
TP39 TP41 TP44 TP47-TP49 TP51-TP53 TP101 = TESTPOINT: TESTPOINT CIR 20 SMD; Chkd/date: SHREESHAIL/171006; Crtd /date: MAZHAR/171006; Custom_Duty: NA; Customs_HS_Code: NA; Distributor_name: NA; Distributor_part_number: NA; Footprint Path: Y:\MIS_DATABASE\Library\ALTIUM_TOOL\PCB_FOOTPRINTS\Altium_Footprint_Lib.PcbLib; Height: NA; Library Path: Y:\MIS_DATABASE\Library\ALTIUM_TOOL\SCHEMATICS_PARTS\MS_DISCRETE_Library.schlib; MECHANICAL 3D STEP FILE: NA; Manufacturer: LOCAL; Mfr_name: LOCAL; Mistral Part No: NA; Package: SMD; Project: BT MODULE_CSRBC04; RoHS: NA; Temperature: NA; Tolerance: NA; Voltage: NA; Wattage: NA; Weight: NA; Datasheet: NA
TP42 TP45 TP46 TP50 TP54 TP100 = TESTPOINT: TESTPOINT CIR 20 SMD; Chkd/date: SHREESHAIL/171006; Crtd /date: MAZHAR/171006; Custom_Duty: NA; Customs_HS_Code: NA; Distributor_name: NA; Distributor_part_number: NA; Footprint Path: Y:\MIS_DATABASE\Library\ALTIUM_TOOL\PCB_FOOTPRINTS\Altium_Footprint_Lib.PcbLib; Height: NA; Library Path: Y:\MIS_DATABASE\Library\ALTIUM_TOOL\SCHEMATICS_PARTS\MS_DISCRETE_Library.schlib; MECHANICAL 3D STEP FILE: NA; Mfr_name: LOCAL; Mistral Part No: NA; Package: SMD; Project: BT MODULE_CSRBC04; RoHS: NA; Temperature: NA; Tolerance: NA; Voltage: NA; Wattage: NA; Weight: NA; Datasheet: NA
U22 = TPS65219_QFN32: IC INTEGRATED POWER MANAGEMENT FOR ARM CORTEX-A53 PROCESSOR AND FPGA QFN32; Chkd/date: PRAVEEN/130123; Crtd /date: SHANKAR/110123; Custom_Duty: 15%; Customs_HS_Code: 85423100; Distributor_name: NA; Distributor_part_number: NA; Footprint Path: Y:\MIS_DATABASE\Library\ALTIUM_TOOL\PCB_FOOTPRINTS\Altium_Footprint_Lib.PcbLib; Height: 1.00MM; Library Path: Y:\MIS_DATABASE\Library\ALTIUM_TOOL\SCHEMATICS_PARTS\MS_MISCPOWER_Library.schlib; Mfr_name: TEXAS INSTRUMENTS; Mistral Part No: 142023010008-R; Package: QFN32; Part_type: ICS\POWER\MANAGEMENT; Project: AM62Q-LP_EVM; RoHS: NA; Temperature: -40°C+125°C; Tolerance: NA; Voltage: NA; Wattage: NA; Weight: NA; Datasheet: Y:\MIS_DATABASE\DATASHEETS\ICS\POWER\TPS65219.PDF
U29 = TPS22965DSGT_WSON8: IC 5.7V 6A 1-CHANNEL 16mE ON-RESISTANCE LOAD SWITCH WSON8; Chkd/date: MANIRAJA/080817; Crtd /date: VASANTHA/280714; Custom_Duty: 15%; Customs_HS_Code: 85423100; Distributor_name: DIGIKEY; Distributor_part_number: 296-34943-1-ND; Footprint Path: Y:\MIS_DATABASE\Library\ALTIUM_TOOL\PCB_FOOTPRINTS\Altium_Footprint_Lib.PcbLib; Height: 0.80MM; Library Path: Y:\MIS_DATABASE\Library\ALTIUM_TOOL\SCHEMATICS_PARTS\MS_MISCPOWER_Library.schlib; Mfr_name: TEXAS INSTRUMENTS; Mistral Part No: 142014070020-R; Package: WSON8; Part_type: ICS\POWER\DRIVER; Project: DC_MIST_DIGITAL CARD; RoHS: RoHS; Temperature: -40°C+105°C; Tolerance: NA; Voltage: NA; Wattage: NA; Weight: 11mg; Datasheet: Y:\MIS_DATABASE\DATASHEETS\ICS\POWER\TPS22965-SER.PDF
U59 = SN74LVC1G11DCKR_SC70-6: IC SINGLE 3-INPUT POSITIVE-AND GATE SON6; Chkd/date: MANIRAJA/270121; Crtd /date: ALVY/270121; Custom_Duty: 15%; Customs_HS_Code: 85423100; Distributor_name: DIGIKEY; Distributor_part_number: 296-30120-1-ND; Footprint Path: Y:\MIS_DATABASE\Library\ALTIUM_TOOL\PCB_FOOTPRINTS\Altium_Footprint_Lib.PcbLib; Height: 0.60MM; Library Path: Y:\MIS_DATABASE\Library\ALTIUM_TOOL\SCHEMATICS_PARTS\MS_GATE_Library.schlib; Mfr_name: TEXAS INSTRUMENTS; Mistral Part No: 141021010013-R; Package: SON6; Part_type: ICS\DIGITAL\GATES; Project: AM64X_SKEVM; RoHS: RoHS; Temperature: -40°C+125°C; Tolerance: NA; Voltage: NA; Wattage: NA; Weight: 33mg; Datasheet: Y:\MIS_DATABASE\DATASHEETS\ICS\DIGITAL\GATES\SN74LVC1G_NOV16.PDF

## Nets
DGND: C69.1 C70.2 C76.2 C79.1 C82.2 C84.1 C85.2 C87.2 C96.2 C100.2 C101.2 C102.2 C107.2 C116.1 C117.2 C118.1 C350.1 C354.1 C359.2 C361.1 C363.1 C364.2 D1.1 R379.2 R411.1 SW1.1 SW1.4 U22.15(AGND) U22.33(PGND) U29.5(GND) U29.9(EP) U59.2(GND) ; also on sheet 1 2 3 13 14 15 16 17 18 19 20 21 22 23 24 25 26 27 28 29 30 31 32 33 34 35 36 37 38 39 40 41 42 43
VCC1V1: C107.1 L3.2 R578.2 TP49.1(TP) U22.24(FB_B3) ; also on sheet 16
VCC1V8_SYS: C82.1 C364.1 L2.2 TP44.1(TP) U22.20(PVIN_LDO2) U22.32(FB_B2) ; also on sheet 16 19 20 22 25 34 37 39 40 42
VCC_0V85: C100.1 TP51.1(TP) U22.19(VLDO2) ; also on sheet 16
VCC_3V3_MAIN: C76.1 C84.2 C85.1 C117.1 C118.2 C350.2 C354.2 C359.1 C361.2 C363.2 R105.1 R210.2 R382.1 R404.2 U22.4(PVIN_B1_1) U22.5(PVIN_B1_2) U22.6(PVIN_LDO1) U22.13(VSYS) U22.22(PVIN_LDO34) U22.26(PVIN_B3) U22.30(PVIN_B2) U29.1(VIN1) U29.2(VIN2) U29.4(VBIAS) U59.5(VCC) ; also on sheet 15 17
VCC_3V3_MAIN_PG: TP101.1(TP) U59.6(C) ; also on sheet 15
VCC_3V3_SYS: C116.2 R122.2 R127.2 R128.2 R130.2 R591.2 TP54.1(TP) U29.7(VOUT1) U29.8(VOUT2) ; also on sheet 1 15 16 19 20 21 23 24 26 27 29 30 31 32 33 34 36 37 38 39 40 41 42 43
VCC_CORE: C70.1 C79.2 L1.2 TP39.1(TP) U22.1(FB_B1) ; also on sheet 16
VDD_1V2: C102.1 TP53.1(TP) U22.23(VLDO4) ; also on sheet 41
VDD_CANUART_EN: R588.2 ; also on sheet 17
VDDA1V8: C101.1 TP52.1(TP) U22.21(VLDO3) ; also on sheet 16
VDDSHV_CANUART: R117.2 ; also on sheet 2 17 31 32
VDDSHV_SDIO: C87.1 TP41.1(TP) U22.7(VLDO1) ; also on sheet 17 21
ETH_CAN_INH_PMIC: R405.2 R590.2 U22.25(EN/PB/VSENSE) ; also on sheet 32
EXTINTn: R126.1 ; also on sheet 42
PMIC_GPO1: R577.2 U22.8(GPO1)
PMIC_INT_B: R122.1 R126.2 TP45.1(TP) U22.11(nINT)
PMIC_MODE: R117.1 R590.1 TP42.1(TP) ; also on sheet 32
PMIC_POWERGOOD: R130.1 TP50.1(TP) U22.18(nRSTOUT) ; also on sheet 42
PMIC_STBY: R591.1 U22.31(MODE/STBY)
PUSH BUTTON: SW1.3 U59.1(A)
RESETSTATz: R403.1 ; also on sheet 1 20 21 22 24 27 32 37 38 39 40 41 42
SoC_I2C0_SCL: R125.1 ; also on sheet 13 23 32 33 37 42
SoC_I2C0_SCL_PMIC: R125.2 U22.10(SCL)
SoC_I2C0_SDA: R123.1 ; also on sheet 13 23 32 33 37 42
SoC_I2C0_SDA_PMIC: R123.2 U22.9(SDA)
TEST_POWERDOWN: U59.3(B) ; also on sheet 14 26 28
TPS65219 EN: R379.1 R382.2 R405.1 TP100.1(TP) U59.4(Y)
TPS65219_GPO: R128.1 TP47.1(TP) U22.16(GPIO)
TPS65219_GPO2: R404.1 R411.2 R588.1 TP48.1(TP) U22.17(GPO2) U29.3(ON)
TPS630702_EN: R210.1 R577.1 R578.1 ; also on sheet 14
VSEL_SD_SOC: R127.1 TP46.1(TP) U22.12(VSEL_SD/VSEL_DDR) ; also on sheet 32
N19361213: R403.2 U22.28(MODE/RESET)
N19361868: L3.1 U22.27(LX_B3)
N19361874: L2.1 U22.29(LX_B2)
N19361880: L1.1 U22.2(LX_B1_1) U22.3(LX_B1_2)
N19361937: C69.2 D1.2 R105.2 SW1.2
N19362078: C96.1 U22.14(VDD1P8)

Not connected (* = marked no-connect by the designer): U29 6(CT)*

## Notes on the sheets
sheet 4
- SOC POWER SUPPLY PMIC
- D-Note :-
  Show the bulk caps connection  for each of
  the DC/DC inputs separately Add a 0.1 uF
  across the bulk caps PVIN_B1_1, PVIN_B1_2 can
  share the same bulk cap
- PMIC REGULATORS
- VOLTAGE RAIL
- CURRENT(mA)
- TPS6521920 PMIC
- BUCK 1
- VCC_CORE(0.75V)
- 3500
- D-Note :-
  Verify the PMIC data sheet for the
  recommended caps for the DC/DC and LDO
  outputs and  provide the recommended
  caps
- D-Note
  Add a 0R resistor or Jumper at the output
  of the DC/DC  for isolation or testing
- BUCK 2
- VCC_1V8
- 2000
- BUCK 3
- VDD_1V1
- 2000
- Input Caps for pin 22,6
- Input Caps for pin 4,5,26,30
- R-Note :-
  Refer PMIC data sheet and
  schematics review checklist for
  reviewing the implementation of
  PMIC section
- LDO 1
- VDDSHV_SDIO
- 400
- Buck1  (3.5A)
- 0.75V
- LDO 2
- VCC_0V85
- 400
- Buck2 (2A)
- LDO 3
- VDDA1V8
- 300
- Buck3 (2A)
- LDO 4
- VDD_1V2
- 300
- SILK SCREEN :
  TP52 - VDDA1V8
  TP53 - VDD_1V2
  TP41 - VDDSHV_SDIO
  TP49 - VCC1V1
  TP39 - VCC_CORE
  TP51 - VCC_0V85
  TP44 - VCC1V8_SYS
- Note: Option Provided for 5V Regulator enabling
- R577
- R210
- R578
- Description
- LDO1 (400mA)
- De mount
- Mount
- De mount
- 5 V Regulator enabled
  by VCC_3V3_MAIN
- LDO2 (400mA)
- De mount
- Demount
- Mount
- 5V Regulator enabled
  by VCC1V1
- LDO3 (300mA)
- R-Note
  SD card interface IO supply voltage switching (3.3V/1.8V)
  is required to support higher speed data rates
  Refer SOC data sheet for supported rates and IO voltage
  levels
- LDO4 (300mA)
- HDMI INTERFACE
- 5V Regulator enabled
  by PMIC GPO1
- Mount
- Demount
- Demount
- Configured as EN
- CAD Note:- Tie the feedback after the DC/DC output bulk caps
- MODE/RESET is configured as RESET
  and RESET should be active low
- I2C ADDRESS: 0x30
- MODE/STBY is configured as Mode, Mode is forced PWM
  or auto-PFM, dependent on MODE polarity
- SOC 3.3V IO SUPPLY
- VCC_3V3_SYS LOAD SWITCH
- PMIC ON/OFF PUSH BUTTON LOGIC
- ON/OFF  PUSH BUTTON
- D- Note:- Add a cap (220 pF or higher) to
  the CT pin for SoC IO supply slew rate
  control. SoC IO supplies have slew rate
  requirements
  specified
sheet 5
- AM625-Q1 / AM620-Q1 -LOW POWER STARTER KIT SK (EVM) With TPS6521920 PMIC
- TABLE OF CONTENTS
- Revision Number
- PAGE
- CONTENTS
- PAGE
- CONTENTS
- REV
- E2A
- 01
- TABLE OF CONTENTS
- 23
- CPSW3G RGMII_2 ETHERNET CONN
- VER
- 2.1
- 02
- REVISION HISTORY
- 24
- SOC MAC INTERFACE, SOC CSI AND ETHERNET PHY CLOCK BUFFER, LED DRIVER
- 03
- BLOCK DIAGRAM FOR SK-AM62-LP
- 25
- TEST AUTOMATION
- 04
- BLOCK DIAGRAM XDS110 DEBUGGER
- 26
- BOOT MODE CONFIGURATION BUFFERS, RESISTOR DIVIDERS AND DIP SWITCHES
- 05
- POWER ARCHITECTURE BLOCK DIAGRAM
- 27
- XDS110 DEBUGGER
- 06
- POWER-UP AND POWER-DOWN SEQUENCE
- 28
- SOC JTAG INTERFACE AND JTAG BUFFERS
- 07
- I2C TREE
- 29
- JTAG 20 PIN cTI CONNECTOR AND BUFFERS
- 08
- GPIO MAPPING TABLE
- 30
- FT4232 UART TO USB BRIDGE
- 09
- USB TYPE-C PD CONTROLLER AND POWER SUPPLY
- 31
- SOC LFOSC0 AND SOC BOOTMODE INPUT PINS, PRU HEADER
- 10
- PERIPHERAL POWER SUPPLIES-1
- 32
- USER EXPANSION CONNECTOR
- 11
- PERIPHERAL POWER SUPPLIES-2
- 33
- SOC-MCU DOMAIN IO, OSC0 AND SOC-MCU IO HEADER
- 12
- SOC POWER SUPPLIES - USING PMIC
- 34
- SOC USB INTERFACE,USB1 TYPE A CONNECTOR,VBUS DIVIDER AND POWER SWITCH
- 13
- SOC SUPPLY RAILS CURRENT MONITORING
- 35
- USB0 TYPE-C DRP
- 14
- SOC SUPPLY RAILS AND POWER SUPPLIES
- 36
- SOC OLDI INTERFACE, LCD CONNECTOR AND SOC UART1 FET SWITCH & BUFFER
- 15
- CAPS FOR SOC POWER SUPPLIES AND SOC GROUND VSS
- 37
- SOC CSI + GPIO INTERFACE + 40 PIN CSI MIPI CONNECTOR
- 16
- SOC DDRSS AND LPDDR4 MEMORY DEVICE INTERFACE
- 38
- AUDIO CODEC
- 17
- M.2 INTERFACE AND CONNECTOR
- 39
- IO EXPANDER AND MCASP1 FET SWITCH & BUFFER
- 18
- SOC MMC0.2 INTERFACE AND eMMC FLASH + RESET
- 40
- SOC DPI INTERFACE, DPI TO HDMI TRANSMITTER INTERFACE
- 19
- SD CARD - LOAD SWITCH RESET LOGIC AND DATA INTERFACE
- 41
- SOC RESET AND IOs, FET SWITCH, AND EXTERNAL LVCMOS CLOCK(OSCILLATOR)
- 20
- SOC OSPI/QSPI INTERFACE AND OSPI FLASH
- 42
- SoC PUSH BUTTON RESET INPUTS WITH DEBOUNCE LOGIC FOR RC RESET
- 21
- BOARD ID EEPROM & DIGITAL TEMPERATURE SENSORS
- 43
- EXTERNAL SWITCH FOR CAN FD WKUP
- 22
- CPSW3G RGMII_1 ETHERNET PHY
- 44
- ASSEMBLY NOTES AND MOUNTING HARDWARE
- D-Note :-
- SK/EVM is a device evaluation board or platform. The SK/EVM is not a reference design. In some cases the EVM implementation may deviate from the
  optimum solution to provide a better customer experience or provide flexibility for customers to be able to validate the SOC functionality. TI
  expects and recommends customers to carefully review and follow all requirements defined in the datasheet, silicon errata, and TRM when
  designing their custom board. The information found in the datasheet should always take precedence over the SK/EVM implementation.
- R-Note:-
- * Verify the DNI components configuration with respect to the SK schematics (Use PDF) after completion of board design before board assembly.
  * A standard 5% tolerance resistor can be used for most of the series and parallel pull resistor.
  * Be sure to read through all the D-Notes (Design notes), R-Notes (Review notes) and CAD notes during board design and before start of board build.
  (Refer FAQs listed for additional details)
- KEY LINKS TO COLLATERALS
- Hardware Design Guide :
- https://www.ti.com/lit/an/sprad05b/sprad05b.pdf
- Schematic Design and Review Checklist :
- https://www.ti.com/lit/an/sprad21d/sprad21d.pdf
- PMIC Power Solutions application note :
- https://www.ti.com/lit/an/slvafd0b/slvafd0b.pdf
- DDR Board Design and Layout Guidelines :
- https://www.ti.com/lit/an/sprad06/sprad06.pdf
- SKs (Starter Kits) for reference :
- SK-AM62B, SK-AM62B-P1, SK-AM62-LP, SK-AM62-SIP, SK-AM62A-LP, SK-AM62P-LP
sheet 6
- REVISION HISTORY
- VER #
- DATE
- DESCRIPTION OF CHANGES
- AUTHOR
- REVIEWED  BY
- APPROVED  BY
- 2.01
- 13 APR 2023
- Drafted from E2 Schematics
- Mistral Design Team
- Deepak NS
- Krishna Prasad A
- 2.02
- 13 APR 2023
- Added M.2 screw and standoffs (9774015243R,
  MPMS 002 0005 PH , 3356)
  Changed the value of R339 resistor to 7.5K
  Chnaged the U14 part to TPD2E2U06DRL
- Deepak NS
- Krishna Prasad A
- Mistral Design Team
- Updated SoC Part Number, Enabled Voltage ratings for all the capacitors and added
  Design Review notes
- Moved to DNI : R581, C5, C43, C41, C338, C376, C140, C416, Q4, U1, Y1
- Moved to Mount : R324, 326, R323, R325, R321, R322, R320, R319, R661, R412, R496, R527, C533
- 2.1
- 24 MAY 2024
- C68 - 1uF changed to 2.2uF ; C533 - 0.1uF changed to 2.2uF ; C39 - 4.7uF changed to 1uF ;
  C40 - 0.1uF changed to 4.7uF ; C38,C384,C185,C192 - 1uF changed to 0.1uF ; C62,C53 - 9pF
  changed to 18pF ; C386,C186,C187 - 2.2uF changed to 1uF
- Mistral Design Team
- R124 - 10K_1% changed to Std 10K ; R91,R372,R371,R627,R628 - 22E_1% changed to 0E ;
  R51,R272,R400 - 49.9_1% changed to Std 10K ; R309 - 100K changed to Std 10K ; R630 - 2.2K
  changed to 1.5K ; R119,R147 - 3.4K_1% changed to 3.48K_1%
- LINKS TO KEY FAQs
- https://e2e.ti.com/support/processors-group/processors/f/processors-forum/1279517/faq-am625-q1-or-am620-q1-custom-board-hardware-design-
  collaterals-to-get-started
- https://e2e.ti.com/support/processors-group/processors/f/processors-forum/1285107/faq-am64x-am62x-am62ax-am62px-custom-board-hardware-design---
  collaterals-for-reference-during-schematic-design-and-schematics-review
- https://e2e.ti.com/support/processors-group/processors/f/processors-forum/1337851/faq-am625-q1-am620-q1-custom-board-hardware-design---design-
  and-review-notes-for-reuse-of-sk-am62-lp-schematics
- https://e2e.ti.com/support/processors-group/processors/f/processors-forum/1280721/faq-am625-am623-am625sip-am625-q1-am620-q1-custom-board-hardware-
  design---faqs-related-to-processor-collaterals-functioning-peripherals-interface-and-starter-kit
sheet 7
- AM62x-LOW POWER SKEVM
          BLOCK DIAGRAM
sheet 8
- BLOCK DIAGRAM_XDS110
- D-Note:-
- Please follow SK-AM62P-LP implementations for latest updates on XDS110
sheet 9
- POWER BLOCK DGM
sheet 10
- POWER SEQUENCE
- POWER UP SEQUENCE
- POWER DOWN SEQUENCE
sheet 11
- I2C TREE
sheet 12
- GPIO MAPPING TABLE
